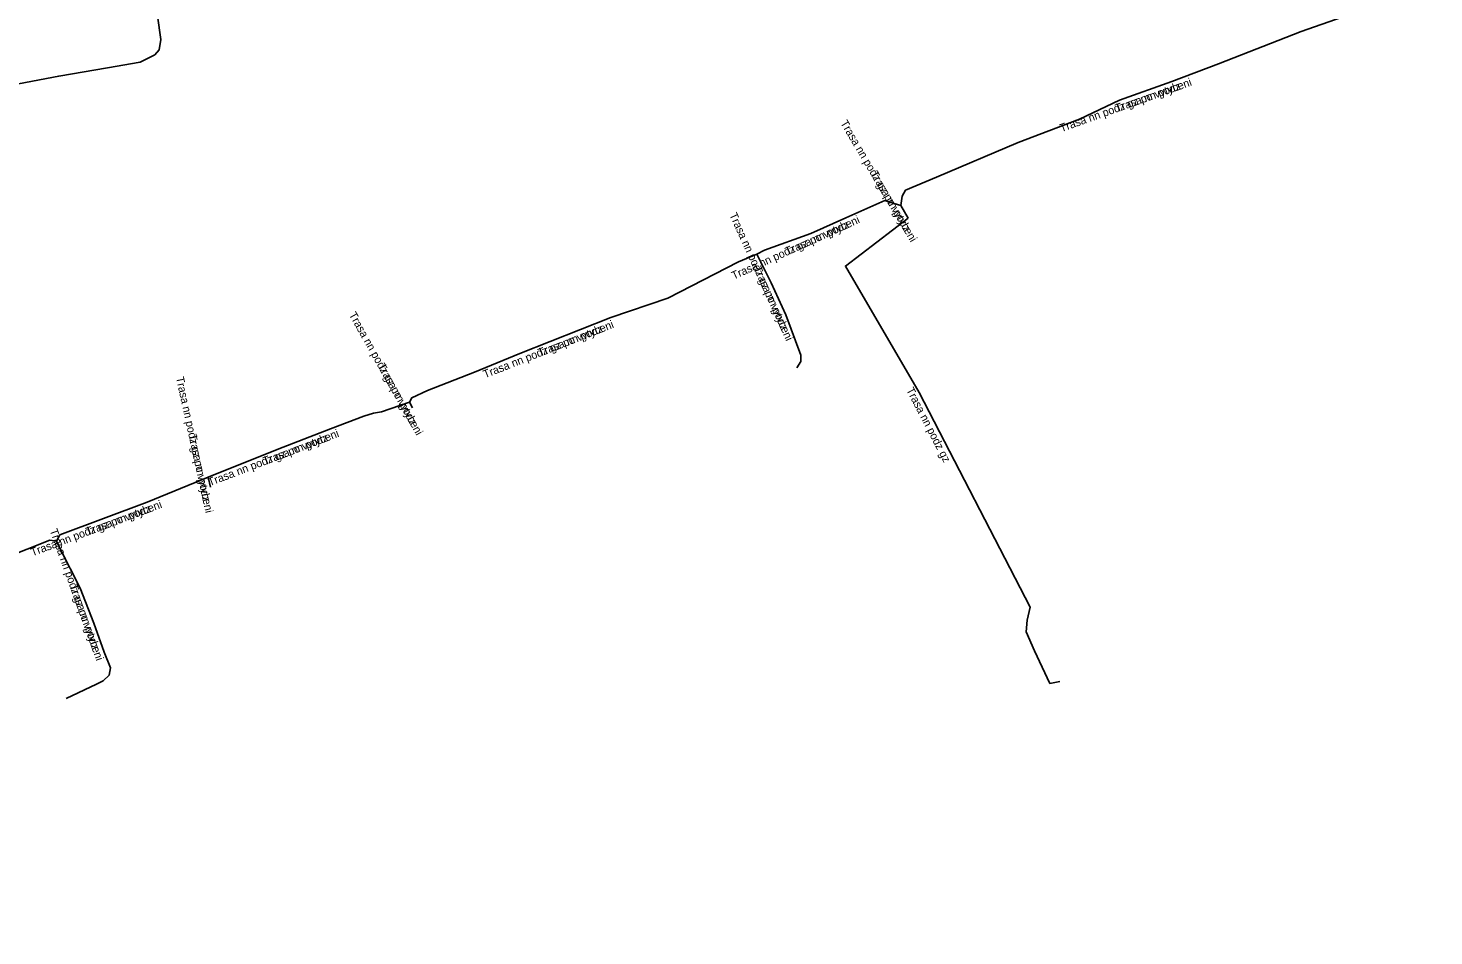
# Model space of a CAD drawing. Extents: x -876384 to -875659, y -1020218 to -1019588.
# Drawn here: x -875879 to -875791.1, y -1019991.2 to -1019934.5 of the extents above; entities that cross this region are included whole.
import ezdxf

# ---------------------------------------------------------------- set-up
doc = ezdxf.new("R2010")
doc.units = 0
doc.layers.add('Popiskový text - Ostatní atributy Trasy', color=7, linetype='Continuous')
doc.layers.add('Spojnice NN', color=7, linetype='Continuous')

msp = doc.modelspace()

# ---------------------------------------------------------------- linework, layer by layer
at = {"layer": 'Spojnice NN'}
for points in [[(-875880.92, -1019938.2), (-875877.07, -1019937.47), (-875874.01, -1019936.95), (-875871.98, -1019936.6), (-875871.05, -1019936.13), (-875870.78, -1019935.83), (-875870.69, -1019935.18), (-875871.1, -1019932.2), (-875871.64, -1019930.3), (-875872.67, -1019923.39), (-875873.67, -1019919.02), (-875873.75, -1019917.98), (-875873.77, -1019917.31), (-875872.64, -1019917.04), (-875869.71, -1019916.57), (-875867.18, -1019916.17), (-875865.68, -1019915.78), (-875860.74, -1019914.13), (-875857.41, -1019913.62), (-875856.86, -1019913.39), (-875856.73, -1019913.06), (-875856.65, -1019912.47), (-875856.84, -1019910.93), (-875857.3, -1019908.09)], [(-875880.92, -1019938.2), (-875877.07, -1019937.47), (-875874.01, -1019936.95), (-875871.98, -1019936.6), (-875871.05, -1019936.13), (-875870.78, -1019935.83), (-875870.69, -1019935.18), (-875871.1, -1019932.2), (-875871.64, -1019930.3), (-875872.67, -1019923.39), (-875873.67, -1019919.02), (-875873.75, -1019917.98), (-875873.77, -1019917.31), (-875872.64, -1019917.04), (-875869.71, -1019916.57), (-875867.18, -1019916.17), (-875865.68, -1019915.78), (-875860.74, -1019914.13), (-875857.41, -1019913.62), (-875856.86, -1019913.39), (-875856.73, -1019913.06), (-875856.65, -1019912.47), (-875856.84, -1019910.93), (-875857.3, -1019908.09)], [(-875824.43, -1019945.56), (-875824.36, -1019944.96), (-875824.14, -1019944.6), (-875822.21, -1019943.79), (-875817.1, -1019941.62), (-875813.27, -1019940.16), (-875810.76, -1019938.98), (-875807.49, -1019937.81), (-875804.59, -1019936.7), (-875799.42, -1019934.68), (-875794.3, -1019932.89), (-875791.98, -1019931.73), (-875791.12, -1019931.59)], [(-875824.43, -1019945.56), (-875824.36, -1019944.96), (-875824.14, -1019944.6), (-875822.21, -1019943.79), (-875817.1, -1019941.62), (-875813.27, -1019940.16), (-875810.76, -1019938.98), (-875807.49, -1019937.81), (-875804.59, -1019936.7), (-875799.42, -1019934.68), (-875794.3, -1019932.89), (-875791.98, -1019931.73), (-875791.12, -1019931.59)], [(-875824.43, -1019945.56), (-875824.86, -1019945.43), (-875825.43, -1019945.25), (-875827.88, -1019946.32), (-875830.05, -1019947.3), (-875832.96, -1019948.34), (-875833.43, -1019948.59)], [(-875824.43, -1019945.56), (-875824.86, -1019945.43), (-875825.43, -1019945.25), (-875827.88, -1019946.32), (-875830.05, -1019947.3), (-875832.96, -1019948.34), (-875833.43, -1019948.59)], [(-875824.43, -1019945.56), (-875823.97, -1019946.34)], [(-875824.43, -1019945.56), (-875823.97, -1019946.34)], [(-875823.97, -1019946.34), (-875827.9, -1019949.34), (-875823.29, -1019957.24), (-875816.36, -1019970.66), (-875816.54, -1019971.47), (-875816.6, -1019972.2), (-875816.08, -1019973.38), (-875815.12, -1019975.41), (-875814.5, -1019975.3)], [(-875833.43, -1019948.59), (-875834.58, -1019949.07), (-875839, -1019951.34), (-875842.55, -1019952.56), (-875848.25, -1019954.8), (-875851.08, -1019955.96), (-875854.01, -1019957.11), (-875854.99, -1019957.56), (-875855.14, -1019957.85)], [(-875833.43, -1019948.59), (-875834.58, -1019949.07), (-875839, -1019951.34), (-875842.55, -1019952.56), (-875848.25, -1019954.8), (-875851.08, -1019955.96), (-875854.01, -1019957.11), (-875854.99, -1019957.56), (-875855.14, -1019957.85)], [(-875833.43, -1019948.59), (-875832.53, -1019950.39), (-875831.63, -1019952.39), (-875830.69, -1019954.91), (-875830.68, -1019955.31), (-875830.94, -1019955.7)], [(-875833.43, -1019948.59), (-875832.53, -1019950.39), (-875831.63, -1019952.39), (-875830.69, -1019954.91), (-875830.68, -1019955.31), (-875830.94, -1019955.7)], [(-875867.72, -1019962.52), (-875863.42, -1019960.79), (-875860.08, -1019959.51), (-875857.99, -1019958.71), (-875857.39, -1019958.53), (-875856.9, -1019958.44), (-875855.14, -1019957.85)], [(-875867.72, -1019962.52), (-875863.42, -1019960.79), (-875860.08, -1019959.51), (-875857.99, -1019958.71), (-875857.39, -1019958.53), (-875856.9, -1019958.44), (-875855.14, -1019957.85)], [(-875855.14, -1019957.85), (-875854.95, -1019958.19)], [(-875855.14, -1019957.85), (-875854.95, -1019958.19)], [(-875877.21, -1019966.53), (-875876.99, -1019966.14), (-875871.53, -1019964.09), (-875867.72, -1019962.52)], [(-875877.21, -1019966.53), (-875876.99, -1019966.14), (-875871.53, -1019964.09), (-875867.72, -1019962.52)], [(-875867.58, -1019963.16), (-875867.72, -1019962.52)], [(-875867.58, -1019963.16), (-875867.72, -1019962.52)], [(-875881.33, -1019991.19), (-875881.67, -1019990.95), (-875882.33, -1019989.09), (-875884.22, -1019984.68), (-875885.52, -1019981.11), (-875886.48, -1019978.82), (-875888.18, -1019974.47), (-875889.12, -1019971.95), (-875889.23, -1019971.38), (-875888.79, -1019971.2), (-875886.76, -1019970.06), (-875881.79, -1019968.1), (-875877.62, -1019966.47), (-875877.21, -1019966.53)], [(-875881.33, -1019991.19), (-875881.67, -1019990.95), (-875882.33, -1019989.09), (-875884.22, -1019984.68), (-875885.52, -1019981.11), (-875886.48, -1019978.82), (-875888.18, -1019974.47), (-875889.12, -1019971.95), (-875889.23, -1019971.38), (-875888.79, -1019971.2), (-875886.76, -1019970.06), (-875881.79, -1019968.1), (-875877.62, -1019966.47), (-875877.21, -1019966.53)], [(-875877.21, -1019966.53), (-875877, -1019966.97), (-875875.72, -1019969.46), (-875874.88, -1019971.64), (-875874.23, -1019973.46), (-875873.84, -1019974.44), (-875873.92, -1019974.9), (-875874.29, -1019975.26), (-875874.71, -1019975.47), (-875876.61, -1019976.35)], [(-875877.21, -1019966.53), (-875877, -1019966.97), (-875875.72, -1019969.46), (-875874.88, -1019971.64), (-875874.23, -1019973.46), (-875873.84, -1019974.44), (-875873.92, -1019974.9), (-875874.29, -1019975.26), (-875874.71, -1019975.47), (-875876.61, -1019976.35)]]:
    msp.add_lwpolyline(points, dxfattribs=at)

# ---------------------------------------------------------------- texts
at = {"layer": 'Popiskový text - Ostatní atributy Trasy'}
for s, rotation, p in [('Trasa nn podz gz po vytyceni', 19.68712, (-875814.397, -1019940.971)), ('Trasa nn podz', 19.68712, (-875810.927, -1019939.73)), ('Trasa nn podz gz po vytyceni', 300.52971, (-875828.231, -1019940.395)), ('Trasa nn podz', 300.52971, (-875826.359, -1019943.569)), ('Trasa nn podz gz po vytyceni', 294.22775, (-875835.16, -1019946.131)), ('Trasa nn podz gz po vytyceni', 24.30455, (-875834.88, -1019950.194)), ('Trasa nn podz', 24.30455, (-875831.522, -1019948.677)), ('Trasa nn podz', 294.22775, (-875833.648, -1019949.491)), ('Trasa nn podz gz po vytyceni', 299.19749, (-875858.945, -1019952.372)), ('Trasa nn podz gz po vytyceni', 21.45396, (-875850.424, -1019956.353)), ('Trasa nn podz', 21.45396, (-875846.994, -1019955.005)), ('Trasa nn podz', 299.19749, (-875857.148, -1019955.589)), ('Trasa nn podz gz po vytyceni', 282.33909, (-875869.745, -1019956.304)), ('Trasa nn podz gz', 297.31153, (-875824.108, -1019957.073)), ('Trasa nn podz', 282.33909, (-875868.958, -1019959.903)), ('Trasa nn podz gz po vytyceni', 20.96851, (-875867.625, -1019963.098)), ('Trasa nn podz', 20.96851, (-875864.184, -1019961.779)), ('Trasa nn podz gz po vytyceni', 20.57904, (-875878.709, -1019967.48)), ('Trasa nn podz', 20.57904, (-875875.259, -1019966.184)), ('Trasa nn podz gz po vytyceni', 289.65382, (-875877.638, -1019965.852)), ('Trasa nn podz', 289.65382, (-875876.398, -1019969.323))]:
    msp.add_text(s, height=0.5, rotation=rotation, dxfattribs=at).set_placement(p)

doc.saveas('drawing.dxf')
